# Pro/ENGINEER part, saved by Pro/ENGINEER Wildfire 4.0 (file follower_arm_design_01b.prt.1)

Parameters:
  METRIC = "NO"

Other parameters: PITCH, DRILL_DIAMETER, THREAD_DIAMETER, THREADS_PER_INCH, THREAD_DEPTH, THREAD_LENGTH, DRILL_POINT_ANGLE, DRILL_DEPTH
